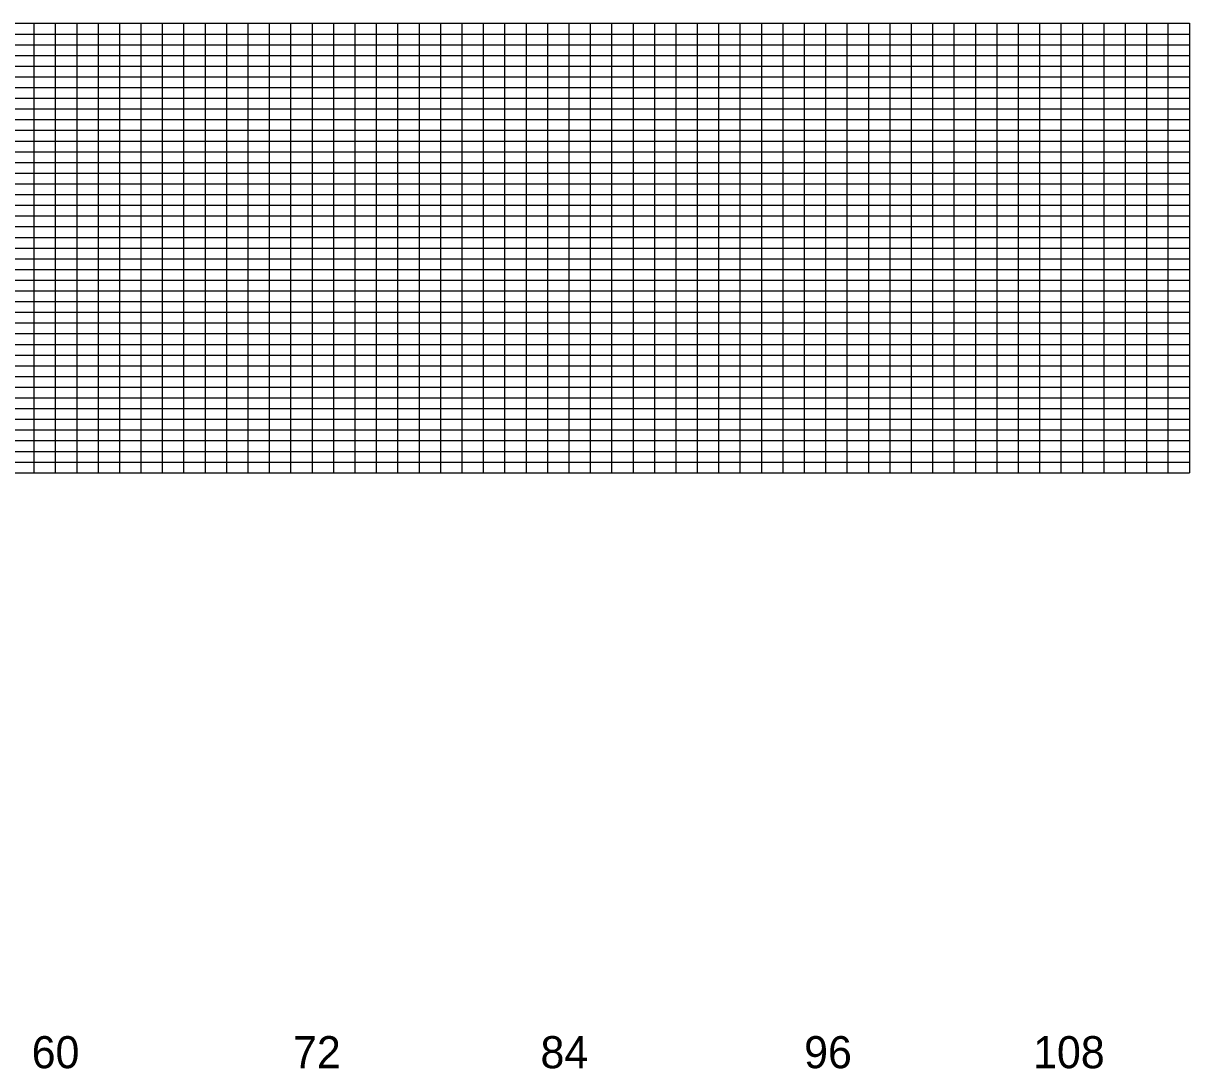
# Model space of a CAD drawing. Extents: x 1914168 to 1925341, y 720939 to 777401.
# Drawn here: x 1917095 to 1919820, y 747072 to 749514 of the extents above; entities that cross this region are included whole.
import ezdxf

# ---------------------------------------------------------------- set-up
doc = ezdxf.new("R2010")
doc.units = 0
doc.layers.add('RD_PD_WallFill', color=7, linetype='Continuous')

msp = doc.modelspace()

# ---------------------------------------------------------------- linework, layer by layer
at = {"layer": 'RD_PD_WallFill'}
for p, q in [((1914470.1, 749514.1), (1919820, 749514.2)), ((1917120.1, 748464.2), (1917120.1, 749514.2)), ((1917170.1, 748464.2), (1917170.1, 749514.2)), ((1917220.1, 748464.2), (1917220.1, 749514.2)), ((1917270.1, 748464.2), (1917270.1, 749514.2)), ((1917320.1, 748464.2), (1917320.1, 749514.2)), ((1917370.1, 748464.2), (1917370.1, 749514.2)), ((1917420.1, 748464.2), (1917420.1, 749514.2)), ((1917470.1, 748464.2), (1917470.1, 749514.2)), ((1917520.1, 748464.2), (1917520.1, 749514.2)), ((1917570.1, 748464.1), (1917570.1, 749514.2)), ((1917620.1, 748464.2), (1917620.1, 749514.2)), ((1917670.1, 748464.2), (1917670.1, 749514.2)), ((1917720.1, 748464.2), (1917720.1, 749514.2)), ((1917770.1, 748464.2), (1917770.1, 749514.2)), ((1917820.1, 748464.2), (1917820.1, 749514.2)), ((1917870.1, 748464.1), (1917870.1, 749514.2)), ((1917920.1, 748464.1), (1917920.1, 749514.2)), ((1917970.1, 748464.2), (1917970.1, 749514.2)), ((1918020.1, 748464.2), (1918020.1, 749514.2)), ((1918070.1, 748464.2), (1918070.1, 749514.2)), ((1918120.1, 748464.2), (1918120.1, 749514.2)), ((1918170.1, 748464.2), (1918170.1, 749514.2)), ((1918220.1, 748464.2), (1918220.1, 749514.2)), ((1918270.1, 748464.2), (1918270.1, 749514.2)), ((1918320.1, 748464.2), (1918320.1, 749514.2)), ((1918370.1, 748464.2), (1918370.1, 749514.2)), ((1918420.1, 748464.2), (1918420.1, 749514.2)), ((1918470.1, 748464.2), (1918470.1, 749514.2)), ((1918520.1, 748464.2), (1918520.1, 749514.2)), ((1918570.1, 748464.2), (1918570.1, 749514.2)), ((1918620.1, 748464.2), (1918620.1, 749514.2)), ((1918670.1, 748464.2), (1918670.1, 749514.2)), ((1918720.1, 748464.2), (1918720.1, 749514.2)), ((1918770.1, 748464.2), (1918770.1, 749514.2)), ((1918820.1, 748464.2), (1918820.1, 749514.2)), ((1918870.1, 748464.2), (1918870.1, 749514.2)), ((1918920.1, 748464.2), (1918920.1, 749514.2)), ((1918970.1, 748464.2), (1918970.1, 749514.2)), ((1919020.1, 748464.2), (1919020.1, 749514.2)), ((1919070.1, 748464.2), (1919070.1, 749514.2)), ((1919120.1, 748464.2), (1919120.1, 749514.2)), ((1919170.1, 748464.2), (1919170.1, 749514.2)), ((1919220.1, 748464.2), (1919220.1, 749514.2)), ((1919270.1, 748464.2), (1919270.1, 749514.2)), ((1919320.1, 748464.2), (1919320.1, 749514.2)), ((1919370.1, 748464.2), (1919370.1, 749514.2)), ((1919420.1, 748464.2), (1919420.1, 749514.2)), ((1919470.1, 748464.2), (1919470.1, 749514.2)), ((1919520.1, 748464.2), (1919520.1, 749514.2)), ((1919570.1, 748464.2), (1919570.1, 749514.2)), ((1919620.1, 748464.2), (1919620.1, 749514.2)), ((1919670.1, 748464.2), (1919670.1, 749514.2)), ((1919720.1, 748464.2), (1919720.1, 749514.2)), ((1919770.1, 748464.2), (1919770.1, 749514.2)), ((1919820.1, 748464.2), (1919820.1, 749514.2)), ((1914920, 749489.1), (1919820, 749489.1)), ((1914920, 749464.1), (1919820, 749464.1)), ((1914920, 749439.1), (1919820, 749439.1)), ((1914920, 749414.2), (1919820, 749414.1)), ((1914920, 749389.1), (1919820, 749389.2)), ((1914470, 749364.1), (1919820, 749364.1)), ((1914470.1, 749339.1), (1919820, 749339.1)), ((1914470, 749314.1), (1919820, 749314.2)), ((1914470, 749289.2), (1919820, 749289.1)), ((1914470, 749264.2), (1919820, 749264.2)), ((1914470, 749239.1), (1919820, 749239.1)), ((1914470, 749214.1), (1919820, 749214.1)), ((1914470, 749189.2), (1919820, 749189.1)), ((1914470, 749164.1), (1919820, 749164.1)), ((1914470, 749139.2), (1919820, 749139.1)), ((1914470, 749114.1), (1919820, 749114.1)), ((1914470, 749089.1), (1919820, 749089.2)), ((1914470, 749064.1), (1919820, 749064.1)), ((1914470, 749039.1), (1919820, 749039.2)), ((1914470, 749014.1), (1919820, 749014.1)), ((1914470, 748989.1), (1919820, 748989.1)), ((1914470, 748964.2), (1919820, 748964.1)), ((1914470, 748939.1), (1919820, 748939.1)), ((1914470, 748914.1), (1919820, 748914.1)), ((1914470, 748889.1), (1919820, 748889.1)), ((1914470, 748864.1), (1919820, 748864.2)), ((1914470.1, 748839.1), (1919820, 748839.1)), ((1914470, 748814.1), (1919820, 748814.1)), ((1914470.1, 748789.1), (1919820, 748789.1)), ((1914470, 748764.1), (1919820, 748764.1)), ((1914470, 748739.1), (1919820, 748739.1)), ((1914470, 748714.1), (1919820, 748714.1)), ((1914470, 748689.1), (1919820, 748689.1)), ((1914470, 748664.1), (1919820, 748664.1)), ((1914470, 748639.1), (1919820, 748639.1)), ((1914470, 748614.1), (1919820, 748614.1)), ((1914470, 748589.1), (1919820, 748589.1)), ((1914470.1, 748564.1), (1919820, 748564.1)), ((1914470, 748539.1), (1919820, 748539.1)), ((1914470, 748514.1), (1919820, 748514.1)), ((1914520, 748489.1), (1919820, 748489.1)), ((1914470, 748464.1), (1919820, 748464.1))]:
    msp.add_line(p, q, dxfattribs=at)

# ---------------------------------------------------------------- texts
for s, p in [('60', (1917114.2, 747072.8)), ('72', (1917724.9, 747072.8)), ('84', (1918303.1, 747072.8)), ('96', (1918919.2, 747072.8)), ('108', (1919454.2, 747072.8))]:
    msp.add_text(s, height=75, dxfattribs=at).set_placement(p)

doc.saveas('drawing.dxf')
